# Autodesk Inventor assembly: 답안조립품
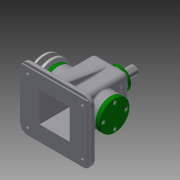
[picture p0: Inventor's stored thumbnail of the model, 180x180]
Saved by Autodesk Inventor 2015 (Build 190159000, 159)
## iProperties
Created: 2016-02
Part Number: 답안조립품
Document SubType Name: Assembly
Designer: Administrator
Author: Administrator
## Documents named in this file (17)
- C:\Users\Administrator\Desktop\460219V1003\답안조립품.iam
- C:\Users\Administrator\Desktop\460219V1003\본체.ipt
- C:\Users\Administrator\Desktop\460219V1003\뒤커버.ipt
- C:\Users\Administrator\Desktop\460219V1003\V-벨트풀리.ipt
- C:\Users\Administrator\Desktop\460219V1003\편심축.ipt
- C:\Users\Administrator\Desktop\460219V1003\키 5 x 5 x 14.ipt
- C:\Users\Administrator\Desktop\460219V1003\링크.ipt
- C:\Users\Administrator\Desktop\460219V1003\상부부시.ipt
- C:\Users\Administrator\Desktop\460219V1003\베어링 15 x 35 x 11.ipt
- C:\Users\Administrator\Desktop\460219V1003\앞커버.ipt
- C:\Users\Administrator\Desktop\460219V1003\와셔.ipt
- C:\Users\Administrator\Desktop\460219V1003\볼트 M6 x 12.ipt
- C:\Users\Administrator\Desktop\460219V1003\고정핀.ipt
- C:\Users\Administrator\Desktop\460219V1003\멈춤링 6 x 5.ipt
- C:\Users\Administrator\Desktop\460219V1003\슬라이드바.ipt
- C:\Users\Administrator\Desktop\460219V1003\멈춤링 15 x 1.ipt
- C:\Users\Administrator\Desktop\460219V1003\볼트 M4 x 10.ipt
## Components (11 placed, 4 different names)
1. V-벨트풀리:1
2. ISO 4018 M6 x 12:1
3. 고정핀:1
4. ISO 4762 M4 x 10:1
5. ISO 4762 M4 x 10:2
6. ISO 4762 M4 x 10:3
7. ISO 4762 M4 x 10:4
8. ISO 4762 M4 x 10:5
9. ISO 4762 M4 x 10:6
10. ISO 4762 M4 x 10:7
11. ISO 4762 M4 x 10:8
